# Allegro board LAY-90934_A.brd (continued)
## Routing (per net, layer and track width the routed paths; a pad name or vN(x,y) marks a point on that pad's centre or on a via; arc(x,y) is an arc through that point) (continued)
N117439837: length 3
  TOP w0.086: U15.9 119.99,60.73 120.14,60.58 v1(120.14,59.82) R131.1
N117439852: length 2.5
  TOP w0.086: U15.10 120.12,61.23 120.4,60.96 120.4,60.58 R123.1
N117439873: length 2.1
  TOP w0.086: U15.11 v1(120.26,61.73) R119.1
N117439950: length 1.9
  TOP w0.086: U15.12 120.77,62.23 R116.1
N117439995: length 1.9
  TOP w0.086: R110.1 120.77,62.73 U15.13
N117440027: length 2.1
  TOP w0.086: U15.14 v1(120.08,63.23) 120.26,63.23 R101.1
N117440047: length 2.5
  TOP w0.086: U15.15 119.99,63.73 120.52,64.26 120.52,64.52 R99.1
N117440102: length 2.9
  TOP w0.086: R95.1 v1(120.14,65.15) 120.14,64.52 119.86,64.23 U15.16
N117440157: length 3.8
  TOP w0.086: R75.1 119.63,65.79 v1(119.13,65.79) 118.62,65.79 118.46,65.63 U15.17
N117440173: length 2.4
  TOP w0.086: R74.1 118.74,66.17 118.36,66.17 v1(118.11,65.91) 117.96,65.77 U15.18
N117440199: length 2
  TOP w0.086: R73.1 117.46,65.9 U15.19
N117440226: length 1.7
  TOP w0.086: R72.1 116.96,66.42 v1(116.96,65.91) U15.20
N117440257: length 1.7
  TOP w0.086: R71.1 116.46,66.42 U15.21
N117440277: length 2
  TOP w0.086: U15.22 v1(115.96,65.9) R70.1
N117440294: length 2.4
  TOP w0.086: R69.1 v1(114.81,66.04) 115.19,66.04 115.46,65.77 U15.23
N117440315: length 2.7
  TOP w0.086: U15.24 114.96,65.38 114.81,65.53 114.3,65.53 v1(113.79,66.04) R68.1
N117440815: length 1.9
  TOP w0.086: U30.13 116.37,30.07 v1(116.14,29.85) 115.82,29.53 R266.1
N117440819: length 1.9
  TOP w0.086: R265.1 v1(111.38,30.1) 111.92,30.64 U29.13
N117440823: length 1.6
  TOP w0.086: U9.13 114.46,71.97 v1(114.17,72.26)
  BOTTOM w0.086: v1(114.17,72.26) 114.43,72.52 R404.1
N117441408: length 3.1
  TOP w0.086: U31.13 126.78,30.39 v1(126.49,30.1)
  BOTTOM w0.086: R465.2 R467.2 v1(126.49,30.1)
N117441414: length 1.8
  TOP w0.086: U10.13 97.44,71.59 v1(96.9,72.14) R39.1
N117441435: length 1.9
  TOP w0.086: U27.13 79.79,36.03 v1(79.25,36.58)
  BOTTOM w0.086: R442.1 v1(79.25,36.58)
N117446518: length 2.8
  TOP w0.381: U36.4 32.35,22.99 v1(33.27,22.99) R299.1 R289.2
N117446570: length 3.8
  TOP w0.381: R298.1 v1(28.7,22.99) 29.63,22.99 U36.3 ; R298.1 R288.2 ; R298.1 28.06,21.88 D29.C
N117446967: length 2
  TOP w0.254: C181.1 v1(17.97,14.03) 17.97,14.72 U47.A6
N117446993: length 1.7
  TOP w0.086: U47.A3 19.5,13.64 C183.1
N117447048: length 2.1
  TOP w0.086: R367.2 19.94,14.09 v1(19.94,14.35) 19.9,14.39 U47.A2
N117447064: length 2.5
  TOP w0.086: R340.2 21.32,16.76 v1(21.21,16.66) U47.E1
  BOTTOM w0.086: v1(21.21,16.66) 21.31,16.76 R475.2
N117447556: length 6.7
  TOP w0.254: D24.C v1(28.57,21.08) D25.C C164.1 28.6,19.43 U46.2
N117447734: length 1.8
  TOP w0.086: U51.C3 27.89,13.66 TP166.1
N117451840: length 1.8
  TOP w0.086: U35.14 94.78,28.74 R263.2
N117451860: length 1.7
  TOP w0.086: U35.13 v1(94.49,28.34) 94.76,28.07 R267.2
N117452169: length 1.8
  TOP w0.086: R271.1 v1(87.5,27.68) 87.75,27.94 U35.39
N117457136: length 4.6
  TOP w0.254: U32.3 138.44,29.73 R269.1 C122.2 135.13,28.32 R268.2
N117457322: length 2.8
  TOP w0.254: R277.2 R273.2 v1(140.85,27.93) 140.45,28.33 U32.6
N117457326: length 1.6
  TOP w0.254: C123.1 v1(138.6,28.88) U32.4
N117457386: length 1.6
  TOP w0.086: TP142.1 141.09,29.73 U32.7
N117457835: length 1.8
  TOP w0.086: R318.1 v1(140.59,18.92) D27.A
N117457859: length 3
  TOP w0.086: R355.1 136.91,17.4 137.29,17.4 137.8,17.91 v1(137.8,18.29) 138.03,18.52 U44.2
N117457920: length 2.5
  TOP w0.086: R356.1 138.43,17.9 U44.3
N117457977: length 2.3
  TOP w0.086: U44.4 v1(138.83,18.29) 138.83,17.29 R357.1
N117458015: length 2.2
  TOP w0.086: R358.1 v1(139.45,17.46) 139.23,17.68 U44.5
N117458076: length 1.6
  TOP w0.086: D26.A 135.38,18.04 v1(135.38,18.8) R322.1
N117458080: length 2.5
  TOP w0.086: U44.12 v1(136.14,19.69) 136.14,19.69 R316.1
N117458344: length 2
  TOP w0.086: J8.55 125.57,6.36 125.57,4.47 TP177.1
N117462626: length 2.6
  TOP w0.086: R5.2 R11.1 v1(87.51,77.34) 87.63,77.22 U6.C2
N117462672: length 3.8
  TOP w0.381: D1.4 v1(74.56,81.78)
  BOTTOM w0.381: v1(74.56,81.78) 73.01,81.78 R390.1
N117462674: length 7.2
  TOP w0.381: D1.3 74.56,78.37 74.93,78.74 76.71,78.74 76.96,78.99 v1(76.96,81.15)
  BOTTOM w0.381: v1(76.96,81.15) R388.1
N117462676: length 2.5
  TOP w0.381: D1.1 v1(76.06,81.78)
  BOTTOM w0.381: v1(76.06,81.78) 75.81,81.78 R389.1
N117462986: length 2.4
  BOTTOM w0.254: R395.2 R396.1 72.9,76.89 Q13.1
N117462992: length 2.4
  BOTTOM w0.254: R391.2 R392.1 78.61,77.01 Q11.1
N117463000: length 2.4
  BOTTOM w0.254: Q12.1 75.82,77.01 R394.1 R393.2
N117463075: length 2.5
  TOP w0.086: U67.C2 87.38,83.31 v1(87.26,83.43) R2.1 R1.2
N117463350: length 6.3
  TOP w0.086: SW1.3 v1(15.88,79.7) SW1.4 17.03,78.76 R10.1
N117463581: length 7.5
  TOP w0.086: SW2.4 SW2.3 23.24,79.68 v1(23.24,77.47) R14.1
N117466193: length 2.8
  TOP w0.086: U56.1 3.64,7.07 2.67,6.1 v1(2.16,6.1) R379.1
N117466207: length 2.8
  TOP w0.086: R12.1 v1(2.67,76.97) 3.64,77.93 U4.1
N117466246: length 3.3
  TOP w0.086: R371.2 v1(2.29,10.8) 2.29,10.29 3.64,8.93 U56.2
N117466262: length 2.8
  TOP w0.086: U4.2 3.64,79.8 2.67,80.77 v1(2.16,80.77) R4.2
N117466578: length 3
  TOP w0.086: R384.1 v1(79.38,5.33) 79.38,6.23 80.22,7.07 U57.1
N117466582: length 2.8
  TOP w0.086: R13.1 79.25,76.97 80.22,77.93 U5.1
N117466611: length 2.5
  TOP w0.086: R372.2 v1(79.63,10.29) 79.63,9.53 80.22,8.93 U57.2
N117466616: length 2.9
  TOP w0.086: U5.2 80.22,79.8 v1(78.99,81.03) R3.2
N117466869: length 3.4
  TOP w0.254: U7.4 10.6,73.34 R26.1 R18.2 C22.2
N117466881: length 4.6
  TOP w0.086: R17.2 3.31,73.91 4.32,73.91 5.14,73.09 6.45,73.09 U7.3
N117474140: length 5
  TOP w0.254: v1(11.18,28.32) 11.3,28.2 U28.9
  BOTTOM w0.381: v1(11.18,28.32) 11.18,27.43 11.21,27.4 C302.1 11.21,24.85 L16.2
N117474237: length 1.7
  TOP w0.086: C180.1 5.69,13.46 v1(5.78,13.55) U50.4
N117474317: length 3
  BOTTOM w0.086: R403.1 55.4,72.65 56.39,71.66 56.39,70.87 56.68,70.58 U60.4
N117474345: length 1.8
  BOTTOM w0.086: U60.5 57.06,72.01 56.41,72.65 R402.1
N117474374: length 2.8
  BOTTOM w0.086: U60.1 56.68,69.38 56.39,69.09 56.39,68.45 R412.1
N117474402: length 1.6
  BOTTOM w0.086: R411.1 57.06,68.1 U60.16
N117474428: length 4.9
  TOP w0.254: v1(8.51,28.19) 8.8,27.9 U28.4
  BOTTOM w0.381: L17.2 8.48,24.98 C303.1 8.48,27.4 C293.1 v1(8.51,28.19)
N117474503: length 1.4
  BOTTOM w0.086: R410.2 57.46,67.49 U60.15
N117474505: length 1.5
  BOTTOM w0.086: R401.1 57.46,72.6 U60.6
N117474615: length 1.4
  BOTTOM w0.086: U60.13 58.26,67.59 R409.2
N117474617: length 1.5
  BOTTOM w0.086: R400.1 58.26,72.49 U60.8
N117475319: length 2.1
  TOP w0.086: TP122.1 18.12,35.02 U28.29
N117475358: length 2
  TOP w0.086: TP114.1 18.36,36.52 U28.32
N117475382: length 3
  TOP w0.086: U28.33 14.8,39.06 16.13,40.39 TP101.1
N117475402: length 2.6
  TOP w0.086: TP100.1 15.11,40.39 14.3,39.57 U28.34
N117475466: length 1.1
  TOP w0.086: D17.A R219.1
N117475515: length 1.3
  TOP w0.086: R226.1 10.05,42.3 D16.A
N117475774: length 2.3
  TOP w0.086: TP97.1 7.3,40.71 U28.48
N117475802: length 2.1
  TOP w0.086: TP123.1 3.21,35.02 U28.52
N117475809: length 3.3
  TOP w0.086: R282.2 C135.1 13.8,24.81 v1(13.8,25.46) U28.14
N117475826: length 3.6
  TOP w0.086: U28.6 v1(9.8,25.89) 10.03,25.65 10.92,25.65 R284.1
N117476127: length 2
  BOTTOM w0.086: R418.1 48.01,67.56 U62.7
N117476217: length 1.8
  BOTTOM w0.086: R416.1 49.28,67.5 49.01,67.77 U62.5
N117476285: length 2.9
  TOP w0.086: U13.22 v1(40.77,69.6) 40.76,69.6 R60.2 R64.2
N117476287: length 4.7
  TOP w0.086: U13.18 42.69,72.37 v1(41.4,73.66) R21.1 R38.2
N117476313: length 1.7
  BOTTOM w0.086: R398.1 48.01,72.52 48.01,72.51 U62.2
N117476531: length 1.5
  TOP w0.086: D5.A v1(30.61,62.48) R112.2
N117476554: length 1.6
  TOP w0.086: U13.8 47.49,69.1 TP15.1
N117476682: length 1.7
  TOP w0.086: U14.1 40.51,65.52 v1(41.03,66.05) R86.2
N117476684: length 1.4
  TOP w0.086: TP13.1 43.19,73.14 U13.17
N117476744: length 3.7
  TOP w0.086: U14.2 v1(40,66.04) R78.1 39.87,66.55 R77.2
  BOTTOM w0.086: R425.1 40.39,65.66 v1(40,66.04)
N117477451: length 2.5
  TOP w0.086: Q3.3 R172.2 5.21,51.94 v1(5.21,51.44) R178.2
N117477453: length 2.5
  TOP w0.086: Q4.3 R187.2 5.21,49.14 v1(5.21,48.64) R194.2
N117477455: length 2.5
  TOP w0.086: R212.2 v1(5.21,45.85) 5.07,45.98 R198.2 Q5.3
N117477457: length 1.5
  TOP w0.086: R206.2 12.82,45.23 v1(12.19,45.23) D15.A
N117477459: length 7.7
  TOP w0.086: R225.2 5.21,42.93 v1(5.08,43.05) 5.08,43.68 R221.2 Q6.3 11.29,43.69 D15.C
N117477506: length 13
  TOP w0.086: R259.1 v1(80.14,31.38) ; D20.C v1(70.87,27.05)
  BOTTOM w0.086: v1(80.14,31.38) 75.82,27.05 v1(70.87,27.05)
N117477781: length 2.7
  TOP w0.086: J7.7 v1(79.25,23.37) R301.1
N117477804: length 2.7
  TOP w0.086: J7.9 v1(80.52,23.37) R302.1
N117479041: length 2.3
  TOP w0.086: SW3.2 64.01,71.12 v1(63.25,71.88) R27.2
N117479043: length 2
  TOP w0.086: R29.2 v1(65.28,72.01) SW3.4
N117479045: length 2
  TOP w0.086: R30.2 v1(66.55,72.01) SW3.6
N117479047: length 2.3
  TOP w0.086: R32.2 v1(68.58,72.01) 68.58,71.76 67.82,70.99 SW3.8

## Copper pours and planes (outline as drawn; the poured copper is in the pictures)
5V_PG on TOP: 46.35,19.94 46.35,17.91 46.1,17.65 44.07,17.65 43.31,18.42 42.42,18.42 42.42,19.05 45.85,19.05 46.1,19.3 46.1,19.94
GND on TOP: 57.53,46.1 54.99,46.1 54.99,42.8 57.53,42.8
GND on TOP: 43.05,23.75 43.05,26.04 37.85,26.04 37.85,23.62 42.93,23.62
GND on TOP: 135.76,43.69 135.76,36.58 135.51,36.32 126.87,36.32 126.36,36.83 126.36,42.29 127.76,43.69
GND on TOP: 91.06,84.2 91.06,81.28 91.31,81.03 92.58,81.03 92.84,81.28 92.84,84.2 92.58,84.46 91.31,84.46
GND on TOP: 41.66,42.42 41.66,45.97 39.12,45.97 39.12,42.42
GND on TOP: 51.56,1.78 51.56,10.16 51.82,10.41 53.97,10.41 53.97,7.49 54.36,7.11 54.36,6.73 53.72,6.73 53.72,1.52 51.82,1.52
GND on TOP: 90.8,76.58 90.8,74.17 92.58,74.17 92.84,74.42 92.84,76.33 92.58,76.58
GND on TOP: 0.51,85.47 0.66,85.83 1.02,85.98 144.4,85.98 144.76,85.83 144.91,85.47 144.91,31.12 144.65,30.86 141.99,30.86 141.73,31.12 139.32,31.12 139.32,33.27 139.06,33.53 135.13,33.53 134.87,33.27 134.87,32.13 134.62,31.88 131.7,31.88 131.45,32.13 131.45,34.29 131.7,34.54 139.57,34.54 140.08,35.05 140.08,46.36 139.83,46.61 139.83,72.77 141.61,74.55 141.61,76.96 143.38,78.74 143.38,84.71 142.88,85.22 1.78,85.22 1.27,84.71 1.27,73.91 1.78,73.41 4.06,73.41 5.33,72.14 5.33,69.72 4.83,69.22 1.78,69.22 1.27,68.71 1.27,5.33 1.78,4.83 4.45,4.83 5.21,4.06 37.46,4.06 39.12,5.72 39.12,9.53 42.8,9.53 43.05,9.27 43.05,5.21 47.88,5.21 47.88,7.49 48.13,7.75 50.8,7.75 51.05,7.49 51.05,1.52 51.56,1.02 78.49,1.02 80.77,3.3 82.8,3.3 82.93,3.18 82.93,0.51 1.02,0.51 0.66,0.66 0.51,1.02 0.51,4.06 0.51,4.06 0.51,31.37 0.51,31.37
GND on TOP: 46.1,24 47.37,24 47.37,18.8 47.62,18.8 47.62,19.94 49.91,19.94 49.91,14.73 47.37,14.73 47.37,18.29 47.12,18.54 47.12,19.94 46.1,20.96
GND on TOP: 16,24.13 16,21.34 23.5,21.34 23.62,21.46 23.62,24.13
GND on TOP: 143,25.53 144.65,25.53 144.91,25.27 144.91,1.02 144.76,0.66 144.4,0.51 142.75,0.51 112.52,0.51 112.52,1.65 104.27,1.65 104.27,0.51 102.87,0.51 102.87,4.7 112.01,4.7 115.32,1.4 139.7,1.4 140.21,1.91 140.21,4.06 142.75,6.6 142.75,25.27
GND on TOP: 16.13,50.29 16.13,51.31 16.51,51.31 16.51,52.83 15.11,52.83 15.11,53.85 14.35,53.85 14.1,53.59 14.1,48.39 14.35,48.13 15.62,48.13 15.75,48.26 15.75,49.91
GND on TOP: 60.32,25.53 60.32,23.62 63.88,20.07 65.02,20.07 65.28,19.81 66.42,19.81 66.42,25.53
GND on BOTTOM: 51.82,38.23 51.94,38.1 52.45,38.1 53.72,39.37 53.72,40.26 53.47,40.51 51.82,40.51
GND on BOTTOM: 89.03,31.12 89.03,27.81 89.41,27.43 94.36,27.43 94.36,31.12 94.23,31.24 89.15,31.24
GND on BOTTOM: 47.24,46.48 49.53,46.48 49.78,46.23 49.78,44.7 50.04,44.45 50.04,44.2 49.78,43.94 49.78,43.18 50.04,42.93 50.04,42.55 49.78,42.29 49.78,41.53 49.66,41.4 46.99,41.4 46.86,41.53 46.86,43.18 46.61,43.43 46.61,43.69 46.86,43.94 46.86,44.7 46.61,44.96 46.61,45.21 46.99,45.59 46.99,46.23
GND on BOTTOM: 0.51,85.47 0.66,85.83 1.02,85.98 144.4,85.98 144.76,85.83 144.91,85.47 144.91,1.02 144.76,0.66 144.4,0.51 112.52,0.51 112.52,1.4 137.54,1.4 142.75,6.6 142.75,30.99 140.08,33.66 140.08,84.71 139.57,85.22 1.78,85.22 1.27,84.71 1.27,73.91 1.78,73.41 4.06,73.41 5.33,72.14 5.33,69.72 4.83,69.22 1.78,69.22 1.27,68.71 1.27,5.33 1.78,4.83 4.45,4.83 7.24,2.03 50.55,2.03 51.56,1.02 78.49,1.02 80.77,3.3 83.19,3.3 83.19,0.51 1.02,0.51 0.66,0.66 0.51,1.02
GND on L2_GND: 0.51,85.47 0.66,85.83 1.02,85.98 144.4,85.98 144.76,85.83 144.91,85.47 144.91,1.02 144.76,0.66 144.4,0.51 112.52,0.51 112.52,1.65 104.27,1.65 104.27,0.51 102.87,0.51 102.87,16.89 97.16,16.89 96.14,15.88 96.14,14.1 95.88,13.84 82.8,13.84 82.04,13.08 82.04,11.05 82.8,10.29 82.8,0.51 1.02,0.51 0.66,0.66 0.51,1.02
GND_CHASSIS on L2_GND: 97.41,16.38 102.36,16.38 102.36,0.51 83.31,0.51 83.31,10.54 82.55,11.3 82.55,12.57 83.31,13.34 96.14,13.34 96.65,13.84 96.65,15.62
VBUS_IN on TOP: 49.91,25.53 59.82,25.53 59.82,23.62 63.12,20.32 63.12,18.03 63.37,17.78 65.15,17.78 65.66,18.29 65.66,18.92 65.79,19.05 67.31,19.05 67.44,18.92 67.44,16.38 61.59,16.38 61.34,16.64 61.34,19.81 58.42,22.73 47.75,22.73 47.75,24 49.66,24 49.66,25.27
VBUS_IN on BOTTOM: 48.64,22.61 48.64,24 48.89,24.26 50.04,24.26 50.29,24 50.29,22.86 50.04,22.61
VCC_ANA_1V8 on TOP: 33.4,45.47 33.4,42.93 33.15,42.67 31.24,42.67 30.99,42.93 30.99,45.47 31.24,45.72 33.15,45.72
VCC_ANA_1V8 on L3_PWR: 98.55,64.39 99.57,63.37 99.57,54.1 93.09,54.1 93.09,56.01 91.06,58.04 62.86,58.04 62.86,47.5 62.1,46.74 35.56,46.74 33.15,44.32 30.99,44.32 30.99,46.1 35.69,50.8 48.64,50.8 48.89,51.05 54.61,51.05 59.69,56.13 59.69,63.5 60.58,64.39
VCC_FT_3V3 on L3_PWR: 4.06,64.9 36.45,64.9 36.45,74.17 52.58,74.17 52.58,62.74 47.37,57.53 25.27,57.53 25.27,28.19 13.08,28.19 13.08,11.3 4.06,11.3
VDD_1P8 on TOP: 65.41,31.12 65.41,29.59 63.5,29.59 63.25,29.85 63.25,31.12 64.77,32.64 65.66,32.64 65.66,31.37
VDD_1P8 on TOP: 44.07,41.91 44.07,40.64 43.56,40.13 43.56,35.56 37.34,35.56 37.34,40.64 37.08,40.89 37.08,42.42 37.34,42.67 37.34,44.2 37.08,44.45 37.08,45.72 38.35,45.72 38.61,45.47 38.61,42.16 38.86,41.91
VDD_1P8 on L3_PWR: 65.41,30.48 65.41,28.19 37.34,28.19 37.34,36.96 38.73,38.35 43.56,38.35 43.56,30.48
VDD_1V8 on TOP: 66.42,31.12 66.42,29.59 69.34,29.59 69.34,32.64 66.17,32.64 66.17,31.37
VDD_1V8 on L3_PWR: 71.75,84.58 144.4,84.58 144.4,31.12 144.15,30.86 142.24,30.86 142.24,9.27 115.7,9.27 115.7,26.04 66.04,26.04 66.04,30.48 98.29,30.48 101.22,33.41 101.22,43.56 101.47,43.82 105.79,43.82 111,38.61 111,29.34 120.27,29.34 120.27,20.19 138.3,20.19 138.3,79.25 84.45,79.25 84.45,74.8 71.75,74.8
VDD_3P3 on TOP: 44.07,46.48 44.07,47.37 43.05,48.39 41.4,48.39 40.77,49.02 40.77,50.17 41.27,50.67 41.27,51.94 40.39,51.94 40.13,51.69 40.13,50.55 39.62,50.04 38.1,50.04 37.85,50.29 34.42,50.29 34.42,47.5 36.7,47.5 37.72,46.48
VDD_3V3 on TOP: 7.24,74.93 7.24,75.95 6.98,76.2 2.54,76.2 2.54,74.93
VDD_3V3 on TOP: 39.62,52.96 39.62,51.31 39.37,51.05 38.1,51.05 37.85,50.8 36.58,50.8 36.58,52.96
VDD_3V3 on TOP: 107.19,24.77 107.19,35.31 107.44,35.56 112.52,35.56 112.78,35.31 112.78,34.42 112.27,33.91 111.51,33.91 111,33.4 111,24.77
VDD_3V3 on L3_PWR: 8.76,65.41 8.76,80.77 26.67,80.77 26.67,77.85 46.1,77.85 46.1,84.58 71.25,84.58 71.25,74.3 130.94,74.3 130.94,25.4 137.8,25.4 137.8,20.7 120.9,20.7 120.9,29.85 111.51,29.85 111.51,39.12 107.57,43.05 107.57,66.68 58.17,66.68 56.77,65.28 56.77,56.77 53.59,53.59 43.69,53.59 42.16,52.07 35.18,52.07 28.45,45.34 28.45,28.19 25.78,28.19 25.78,57.02 47.62,57.02 53.09,62.48 53.09,74.68 35.94,74.68 35.94,65.41
VDD_3V3 on L3_PWR: 51.94,25.53 115.19,25.53 115.19,9.14 64.52,9.14 64.52,11.81 65.91,13.21 65.91,19.56 65.41,20.07 51.94,20.07
VDD_5V on TOP: 87.5,82.04 87.5,81.41 87.12,81.03 84.96,81.03 84.71,81.28 84.71,82.42 84.96,82.68 86.61,82.68 87.12,82.17 87.38,82.17
VDD_5V on TOP: 55.12,5.21 55.12,1.78 55.37,1.52 58.29,1.52 58.55,1.78 58.55,5.21
VDD_5V on TOP: 38.86,83.44 38.86,78.36 38.61,78.11 34.8,78.11 34.54,78.36 34.54,83.44 34.8,83.69 38.61,83.69
VDD_5V on BOTTOM: 35.69,78.74 35.69,83.19 51.69,83.19 52.58,84.07 87.5,84.07 87.5,81.41 87.12,81.03 77.98,81.03 77.34,81.66 72.77,81.66 69.85,78.74
VDD_5V on L3_PWR: 57.15,1.02 57.15,6.6 34.67,6.6 33.78,5.72 26.16,5.72 25.27,6.6 20.7,6.6 19.94,5.84 12.07,5.84 11.3,6.6 3.56,6.6 3.56,65.41 8.25,65.41 8.25,81.28 27.18,81.28 27.18,78.36 45.59,78.36 45.59,84.58 0.51,84.58 0.51,1.02
VDD_ANA_0P8 on TOP: 53.21,35.56 53.47,35.31 54.48,35.31 54.74,35.56 54.74,36.32 54.23,36.83 54.23,38.48 53.34,39.37 53.34,40.01 52.07,41.28 52.07,41.53 51.23,42.37 50.44,42.37 50.44,42.16 50.8,42.16 50.93,42.04 50.93,41.4 51.69,40.64 51.69,39.75 52.45,39.75 52.7,39.5 52.7,38.61 52.32,38.23 52.32,36.83 51.69,36.2 51.69,35.56
VDD_ANA_0V8 on TOP: 51.69,34.54 51.69,32.77 51.94,32.51 54.48,32.51 54.74,32.77 54.74,34.54 54.48,34.8 53.47,34.8 53.21,34.54
VDD_ANA_0V8 on L3_PWR: 51.94,33.27 53.59,33.27 54.48,32.39 96.52,32.39 98.93,34.8 98.93,51.82 98.68,52.07 96.65,52.07 96.39,51.82 96.14,51.82 96.14,53.85 96.27,53.98 97.03,53.98 97.28,53.72 104.14,53.72 104.14,47.24 100.71,43.82 100.71,33.66 98.04,30.99 51.69,30.99 51.69,33.02
VDD_ANA_1V8 on TOP: 36.07,42.67 34.16,42.67 33.91,42.93 33.91,45.47 34.16,45.72 36.58,45.72 36.58,44.45 36.32,44.2 36.32,42.93
VDD_SOC on TOP: 95.38,53.85 95.38,52.32 95.25,52.2 93.22,52.2 93.09,52.32 93.09,53.85 93.22,53.98 95.25,53.98
VDD_SOC on TOP: 61.98,37.97 63.5,37.97 63.75,38.23 64.9,38.23 65.15,37.97 65.15,35.31 64.9,35.05 62.23,35.05 61.98,35.31
VDD_SOC on L3_PWR: 95.88,53.34 95.88,52.45 95.76,52.32 95.76,50.55 96.52,49.78 96.52,36.58 94.36,34.42 61.98,34.42 61.98,44.2 88.39,44.2 92.46,48.26 92.46,50.17 92.71,50.42 92.71,51.94 92.96,52.2 92.96,53.34
VDD_SOC_0V85 on TOP: 52.58,42.29 52.58,41.28 53.97,39.88 54.99,39.88 55.24,39.62 55.24,35.31 55.5,35.05 61.21,35.05 61.47,35.31 61.47,37.97 61.21,38.23 58.29,38.23 58.04,38.48 58.04,40.89 58.42,41.28 60.96,41.28 60.96,42.29 59.82,42.29 59.82,42.93 59.56,42.93 59.56,42.29
VDD_USB_3V3 on TOP: 33.91,47.5 32.64,47.5 32.64,50.29 33.91,50.29
DCDC_5V on TOP: 30.61,30.86 30.61,28.45 30.35,28.19 27.81,28.19 27.56,28.45 27.56,30.35 27.81,30.61 29.08,30.61 29.34,30.86
DCDC_5V on TOP: 139.83,30.35 139.83,30.1 141.48,30.1 142.75,28.83 142.75,26.29 143,26.04 144.15,26.04 144.4,26.29 144.4,30.1 144.15,30.35
DCDC_5V on TOP: 37.85,23.11 43.81,23.11 44.07,22.86 44.07,22.48 42.54,22.48 41.02,20.96 41.02,19.56 41.53,19.05 41.91,19.05 41.91,15.37 42.16,15.11 46.23,15.11 47.12,14.22 50.16,14.22 50.16,17.53 51.69,17.53 51.69,12.07 52.2,11.56 58.17,11.56 58.42,11.3 58.42,5.84 58.17,5.59 54.23,5.59 54.23,6.35 54.61,6.35 54.61,7.11 54.86,7.11 54.86,6.35 55.63,6.35 55.63,7.62 55.5,7.75 54.61,7.75 54.48,7.87 54.48,10.54 54.23,10.8 48.26,10.8 45.59,13.46 37.85,13.46
DCDC_5V on TOP: 19.43,17.78 19.43,16.13 20.07,16.13 20.07,17.65 20.57,18.16 23.62,18.16 23.62,20.7 23.5,20.83 19.56,20.83 19.56,17.91
DCDC_5V on L3_PWR: 142.75,30.35 142.75,8.64 64.01,8.64 64.01,11.81 40,11.81 40,20.07 45.08,20.07 45.08,27.69 36.83,27.69 36.83,30.86 28.83,30.86 28.83,27.69 19.56,27.69 19.56,24.64 31.12,24.64 31.12,9.78 23.62,9.78 23.62,20.83 19.56,20.83 19.56,7.11 57.66,7.11 57.66,1.02 104.27,1.02 104.27,1.65 112.52,1.65 112.52,1.02 144.4,1.02 144.4,30.1 144.15,30.35
EXP_3V3 on TOP: 88.77,76.33 88.52,76.07 88.14,76.07 88.01,75.95 88.01,75.31 88.14,75.18 88.14,74.42 88.39,74.17 90.3,74.17 90.3,78.36 90.04,78.61 89.03,78.61 88.77,78.36
EXP_5V on TOP: 90.04,81.03 90.04,84.2 89.79,84.46 88.77,84.46 88.52,84.2 88.52,82.42 88.27,82.17 87.88,82.17 87.76,82.04 87.76,81.41 87.88,81.28 87.88,79.63 90.3,79.63 90.3,80.77
LPD4_VDD1 on TOP: 36.32,39.12 36.32,40.64 36.58,40.89 36.58,41.91 36.32,42.16 34.16,42.16 33.91,41.91 33.91,39.37 34.16,39.12
LPD4_VDD1 on BOTTOM: 73.53,44.7 80.39,44.7 80.64,44.96 80.64,46.23 81.03,46.61 81.03,56.52 80.01,56.52 80.01,51.69 79.5,51.18 79.5,46.23 78.74,45.47 75.31,45.47 74.55,46.23 74.55,56.9 72.9,56.9 72.64,56.64 72.64,55.88 73.53,54.99
LPD4_VDD2 on TOP: 59.94,55.25 65.41,55.25 65.41,51.94 61.72,51.94 61.47,52.2 59.94,52.2
LPD4_VDD2 on TOP: 92.08,54.99 92.46,54.99 92.46,51.11 92.6,50.96 92.84,50.96 92.87,50.93 92.87,50.7 92.76,50.59 92.01,50.59 91.87,50.45 91.87,50.22 91.78,50.13 91.63,50.13 91.51,50.26 91.51,51.02 91.62,51.14 91.86,51.14 92.08,51.36
LPD4_VDD2 on BOTTOM: 92.46,54.99 92.46,54.1 92.58,53.98 92.84,53.98 92.84,53.09 92.46,52.71 92.46,51.18 92.58,51.05 92.84,51.05 92.84,50.67 92.33,50.67 91.82,50.17 91.57,50.17 91.57,50.93 91.31,51.18 89.66,51.18 89.66,51.69 89.79,51.82 91.95,51.82 91.95,53.98 90.3,53.98 90.3,54.48 90.04,54.74 88.27,54.74 85.34,57.66 78.11,57.66 77.85,57.4 77.85,47.88 74.8,47.88 74.8,57.15 74.55,57.4 72.39,57.4 72.14,57.15 72.14,55.75 73.28,54.61 73.28,45.72 63.63,45.72 63.63,54.99 63.88,55.25 65.41,55.25 69.47,59.31 74.3,59.31 76.07,61.09 88.01,61.09 89.92,59.18 89.92,58.42 90.8,57.53 90.8,55.75 91.57,54.99
LPD4_VDD2 on L3_PWR: 63.37,57.66 89.66,57.66 92.46,54.86 92.46,50.55 92.08,50.17 92.08,48.64 88.14,44.7 63.37,44.7
LPD4_VDD2_1V1 on TOP: 56.01,55.25 59.44,55.25 59.44,51.94 59.18,51.69 57.53,51.69 57.02,51.18 57.02,48.39 57.53,47.88 58.8,47.88 59.05,47.63 59.05,46.86 58.8,46.61 52.45,46.61 52.45,47.63 52.7,47.88 55.75,47.88 56.01,48.13 56.01,49.53 55.37,49.53 55.37,49.78 56.01,49.78
LX1 on TOP: 50.44,44.96 50.44,45.57 52.17,45.57 52.7,46.1 54.48,46.1 54.48,44.96
LX2 on TOP: 50.44,43.31 50.44,43.97 54.48,43.97 54.48,42.8 52.45,42.8 51.94,43.31
LX3 on TOP: 46.33,42.93 46.33,43.59 45.24,43.59 45.21,43.56 42.16,43.56 42.16,42.55 44.96,42.55 45.34,42.93
LX4 on TOP: 46.33,44.96 46.33,45.57 44.86,45.57 44.45,45.97 42.16,45.97 42.16,44.96
NVCC_1V8 on TOP: 95.38,51.94 95.38,51.69 94.74,51.69 94.49,51.44 94.49,50.67 93.98,50.67 93.98,51.82 94.11,51.94
NVCC_1V8 on TOP: 33.91,38.35 34.16,38.61 36.7,38.61 36.96,38.35 36.96,37.72 36.32,37.08 36.32,35.81 36.07,35.56 34.16,35.56 33.91,35.81
NVCC_3V3 on TOP: 43.43,48.9 43.69,49.15 43.69,51.69 43.43,51.94 41.91,51.94 41.91,49.15 42.16,48.9
NVCC_3V3 on BOTTOM: 96.01,53.85 96.01,52.83 96.14,52.71 97.41,52.71 97.54,52.83 100.2,52.83 103.76,56.39 103.76,60.71 99.57,64.9 99.19,64.9 98.93,64.64 98.93,64.01 102.74,60.2 102.74,56.9 99.69,53.85
NVCC_SD2 on TOP: 51.18,34.54 51.18,32.77 50.93,32.51 48.89,32.51 48.64,32.77 48.64,34.8 50.93,34.8
NVCC_SD2 on L3_PWR: 98.42,34.93 96.27,32.77 54.74,32.77 53.85,33.66 51.69,33.66 51.05,33.02 48.64,33.02 48.64,36.45 54.1,36.45 56.52,34.04 94.61,34.04 96.9,36.32 96.9,49.91 96.01,50.8 96.01,51.56 98.42,51.56
S1_LPD4_VDD2 on TOP: 57.28,49.53 57.28,50.93 57.53,51.18 61.47,51.18 61.72,51.44 62.99,51.44 62.99,49.53
S1_VDD_SOC_0V8 on TOP: 59.56,41.02 61.21,41.02 61.47,41.28 61.47,42.04 61.72,42.29 64.9,42.29 65.15,42.04 65.15,38.99 64.9,38.74 63.75,38.74 63.5,38.99 61.98,38.99 61.72,38.74 59.82,38.74 59.56,38.99
USB1_VBUS_IN on TOP: 17.65,15.75 17.53,15.62 17.53,14.35 16.76,13.59 16.76,12.19 15.37,12.19 15.11,12.45 15.11,17.4 15.37,17.65 18.16,17.65 18.41,17.4 18.41,15.75
USB_PD_VBUS on TOP: 43.56,5.72 43.56,9.53 47.12,9.53 47.37,9.27 47.37,5.72 46.61,5.72 46.61,7.24 46.1,7.75 44.83,7.75 44.32,7.24 44.32,5.72
USB_PD_VBUS_F on TOP: 63.75,19.56 66.8,19.56 66.8,19.3 65.41,19.3 65.41,18.67 65.02,18.29 63.75,18.29 63.5,18.54 63.5,19.3
USB_PD_VBUS_F on TOP: 39.12,12.7 39.12,10.54 45.34,10.54 45.59,10.8 45.59,12.7 45.34,12.95 39.37,12.95
USB_PD_VBUS_F on L3_PWR: 65.15,19.56 65.41,19.3 65.41,13.72 64.01,12.32 40.51,12.32 40.51,19.56
USBC_VBUS on TOP: 26.67,10.16 26.67,8.26 28.07,8.26 28.07,9.91 27.81,10.16
USBC_VBUS_F on TOP: 18.67,15.75 19.18,15.75 19.18,17.78 19.05,17.91 19.05,20.83 16,20.83 16,18.16 18.03,18.16 18.54,17.65 18.67,17.4
USBC_VBUS_F on L3_PWR: 24.13,10.29 24.13,21.34 19.05,21.34 19.05,18.16 16,18.16 16,24.13 30.61,24.13 30.61,10.29
VEXP_3V3 on TOP: 94.61,78.23 94.61,74.17 93.34,74.17 93.34,76.84 93.09,77.09 91.06,77.09 90.8,77.34 90.8,78.36 91.06,78.61 94.23,78.61
VEXP_5V on TOP: 97.16,84.2 97.16,79.25 91.06,79.25 90.8,79.5 90.8,80.52 93.09,80.52 93.34,80.77 93.34,84.2 93.6,84.46 96.9,84.46
VEXT_3V3 on TOP: 87.76,75.95 87.76,75.31 87.25,74.8 84.96,74.8 84.96,76.07 85.22,76.33 87.12,76.33 87.38,76.07 87.63,76.07
VEXT_3V3 on TOP: 139.32,30.35 139.32,30.1 138.3,30.1 137.16,28.96 134.62,28.96 134.24,28.58 131.45,28.58 131.45,30.86 134.87,30.86 135.13,31.12 137.54,31.12 138.3,30.35
VEXT_3V3 on TOP: 121.41,14.73 121.41,10.8 117.35,10.8 117.35,14.48 117.6,14.73
VEXT_3V3 on TOP: 138.18,14.73 138.18,11.05 138.43,10.8 142.24,10.8 142.24,14.48 141.99,14.73
VEXT_3V3 on BOTTOM: 117.35,14.48 117.35,10.8 142.24,10.8 142.24,30.73 141.99,30.99 131.7,30.99 131.45,30.73 131.45,16.51 131.19,16.26 119.13,16.26
VEXT_3V3 on L3_PWR: 84.96,78.74 84.96,74.8 131.45,74.8 131.45,25.91 137.8,25.91 137.8,78.74
VLDO_3V3 on TOP: 75.31,9.78 75.31,7.87 73.28,7.87 73.28,9.78
VMIC_1V8 on TOP: 9.78,75.06 11.81,75.06 11.94,75.18 11.94,77.47 10.67,77.47 10.29,77.09 7.49,77.09 7.49,76.2 7.75,75.95 7.75,74.93 9.65,74.93
VSD2_3V3 on TOP: 139.57,42.16 139.57,39.88 139.32,39.62 136.53,39.62 136.53,42.42 139.32,42.42
VSD_3V3 on TOP: 136.53,39.12 136.53,38.1 136.78,37.85 136.78,35.31 139.32,35.31 139.57,35.56 139.57,38.86 139.32,39.12
VSYS on BOTTOM: 48.64,40.89 48.64,39.88 48.77,39.75 49.4,39.75 49.53,39.88 49.53,40.89 49.4,41.02 48.77,41.02
VSYS_5V on TOP: 46.33,43.76 46.33,44.78 45.01,44.78 44.96,44.83 43.94,44.83 43.81,44.7 43.81,43.82 43.94,43.69 44.96,43.69 45.03,43.76
VSYS_5V on TOP: 30.61,31.37 30.61,33.91 30.35,34.16 27.81,34.16 27.56,33.91 27.56,31.88 27.81,31.62 29.08,31.62 29.34,31.37
VSYS_5V on TOP: 53.21,44.78 53.21,44.17 50.44,44.17 50.44,44.78
VSYS_5V on BOTTOM: 51.31,39.37 50.16,39.37 49.91,39.62 49.91,41.02 50.29,41.4 50.29,42.55 50.55,42.8 51.69,42.8 51.94,42.55 51.94,41.15 51.31,40.51
VSYS_5V on BOTTOM: 50.42,43.18 50.29,43.31 50.29,43.82 50.42,43.94 50.42,44.7 50.29,44.83 50.29,46.23 50.55,46.48 52.96,46.48 53.21,46.23 53.21,43.43 52.96,43.18
VSYS_5V on BOTTOM: 46.48,45.72 46.35,45.59 46.35,44.83 46.48,44.7 46.48,44.2 46.35,44.07 46.35,43.31 46.48,43.18 46.48,42.29 46.23,42.04 43.56,42.04 43.31,42.29 43.31,46.23 43.56,46.48 46.23,46.48 46.48,46.23
VSYS_5V on L3_PWR: 33.4,43.94 28.83,43.94 28.83,31.37 34.29,31.37 34.54,31.62 34.54,38.1 33.91,38.74 33.91,40.01 34.54,40.64 35.18,40.64 35.94,41.4 45.47,41.4 45.85,41.78 48.51,41.78 49.78,40.51 52.2,40.51 53.09,41.4 53.09,45.85 52.7,46.23 35.69,46.23
N117404173 on TOP: 47.75,21.97 47.75,20.19 50.67,20.19 51.05,19.81 51.05,18.16 51.31,17.91 59.69,17.91 59.69,20.32 58.04,21.97
N117404173 on BOTTOM: 47.88,21.97 47.88,20.45 48.13,20.19 50.04,20.19 50.29,20.45 50.29,21.84 50.04,22.1 48.01,22.1
N117404204 on TOP: 59.69,11.94 59.69,17.27 59.44,17.53 53.21,17.53 52.96,17.27 52.96,11.94
N117456939 on TOP: 138.56,33.02 135.38,33.02 135.38,31.62 137.67,31.62 138.68,30.61 141.35,30.61 141.35,30.86 139.06,30.86 138.81,31.12 138.81,32.77

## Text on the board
BOTTOM: 170-90934 REV A | 7 OF 10 | SECONDARY SIDE (BOTTOM)
Board Geometry/Soldermask Bottom: 8 OF 10 | SECONDARY SOLDERMASK
Ref Des/Silkscreen Bottom: 700-90934 REV X | SCH-90934 REV X | S/N | 9 OF 10 | SECONDARY SILKSCREEN
User.Comments: 22. THIS FAB_VIAFILL.ART SHOWS LOCATIONS OF VIA-IN-PAD TO BE FILLED.
TOP: 4 OF 10 | PRIMARY SIDE (TOP)
Board Geometry/Soldermask Top: 3 OF 10 | PRIMARY SOLDERMASK
Ref Des/Silkscreen Top: K | DOWNLOAD | EMMC | MICROSD | QSPI NAND | 0001 | 0010 | 0011 | 0101 | CS0 | GND | CA0 | TDO | TMS | TDI | TCK | RXC | CLKO1 | RCTL | RD0 | TD0 | DQS | TXC | 1V0 | MDIO | MDC | RST | TCTL | MCLK | D0 | CMD | CLK | TXFS | TXD | BT | WAKE | WiFi | SW3[1:4] | CKI2 | CKI1 | PORB | ON_REQ | STBY | 1V8 | 3V3 | PDM_D1 | PDM_D0 | TX | INT | RX | SCL | SDA | REMOTE DBG | 5V | H | L | WDOG | SCL2 | SDA2 | T0/1 | SCL1 | VBUS | SDA1 | 32K | 24M | R | DAC | PDM | UART | M2 | DET | CAN | JTAG | QSPI | IO21 | PG | OFF | ON | SUSPEND | VDD1_1V8 | NVCC1V8 | USB3V3 | ANA1V8 | VDD3V3 | NVCC3V3 | BBSM | SD2 | ANA0V8 | 0V85 | RXD | SOC_0V85 | 1V1 | TXD/BT3 | VDD_1V8 | TXFS/BT2 | TXD1/BT0 | TXD2/BT1 | RGB LED | ENET | eMMC | ON/OFF | RESET | BOOT MODE | TAMPER | UART1 | I2C CN | PWR | LPDDR4 | I3C | M.2 KEY-E | WiFi/BT | E | MicroSD | DBG | USB1 | PD PWR | BMODE | ADC | AUD | 2 OF 10 | + | - | PRIMARY SILKSCREEN | MX91LP4QSB-09 | EXP CN
L2_GND: 5 OF 10 | LAYER2_GND
L3_PWR: 6 OF 10 | LAYER3_PWR
FABRICATION_NOTES: LAYERS | L1_PS | L4_SS | TRACE WIDTH | 3.40 | SE | IMPEDANCE | 50 | 3.41 | TRACE SPACING | 5.09 | 90 | 3.00 | 6.20 | DIFF | 100 | 3.70 | 4.40 | 85 | REFERENCE LAYER | 2 | 3 | THE ADDITION OF RAIL MUST BE ADDED ON FRONT SIDE & REAR SIDE AND APPROVED BY BOARD DESIGNER. | 23. V-CUT DETAILS:   SEE DETAIL 'D' | 24. PCB vendor change must be reviewed and approved by board designer, | PCB material and stack-up must not be changed. | 19 | 16 | 22 | 4x | 23 | LAYER STACKUP | SCALE:NONE | DETAIL A | DETAIL B | IMPEDANCE REQUIREMENTS | IMPEDANCE TOLERANCE IS 10%
XSECTION_CHART: 1-4 | L1 TOP CONDUCTOR - 1/2OZ_COPPER_PLATED_FOIL 1.4 MIL | *  DIELECTRIC - 185HR 2.072 MIL | L2 L2_GND PLANE - 1OZ_COPPER 1.2 MIL | *  DIELECTRIC - 185HR 52.37 MIL | L3 L3_PWR PLANE - 1OZ_COPPER 1.2 MIL | L4 BOTTOM CONDUCTOR - 1OZ_COPPER_PLATED_FOIL 1.4 MIL | DESIGN CROSS SECTION CHART | ___________________________ | TOTAL THICKNESS 61.714 MIL | BOARD THICKNESS TOLERANCE +/-10% | ALL VALUES ARE FINISHED VALUES. | 1 OF 10 | PRIMARY PASTEMASK
DIMENSION: 10 OF 10 | SECONDARY PASTEMASK | PRIMARY DATUM | GRID ORIGIN | ONLY ON BOTTOM SIDE 2x | 1/3 PCB THICKNESS | BREAKING EDGE | DETAIL-C | TOP SIDE | BOT SIDE
User.8: ALL PARTS, MATERIALS AND FINISHED | ASSEMBLY SHALL NOT CONTAIN ANY OF | THE SUBSTANCES OF VERY HIGH CONCERN | (SVHC) ABOVE THE THRESHOLD VALUE PER | THE CURRENT ECHA LIST OF SVHC'S AND | WITH ANNEX XIV AND ANNEX XVII OF REACH | DIRECTIVE 76/769/EEC. A CERTIFICATE OF | COMPLIANCE IS REQUIRED UPON REQUEST. | ASSEMBLY SHALL MEET THE RoHS | COMMISSION DELEGATED DIRECTIVE (EU) | 2015/863 OF 31 MARCH  2015 AMENDING | ANNEX II TO DIRECTIVE 2011/65/EU. A | CERTIFICATE OF COMPLIANCE IS | REQUIRED UPON REQUEST. | NONE | 1
User.10: FIGURE | FINISHED_SIZE | 8.0 | 8.1 | 16.0 | 28.0 | 32.0 | 35.0 | 40.0 | 63.0 | 80.0 | 166.0 | 26.0 | 33.4 | 37.4 | 39.0 | 43.3 | 59.0 | 67.0 | 68.0 | 128.0 | 44.0x20.0 | 47.0x20.0 | 51.0x20.0 | 59.0x20.0 | DRILL CHART: TOP to BOTTOM | ALL UNITS ARE IN MILS | TOLERANCE_DRILL | +0.0/-8.0 | +0.0/-8.1 | +2.0/-2.0 | +4.0/-0.0 | +3.0/-3.0 | +1.0/-2.0 | +1.0/-1.0 | +2.0/-1.97 | +4.0/-4.0 | PLATED | NON-PLATED | QTY | 1873 | 111 | 24 | 6 | 4 | 16 | 2 | 1
